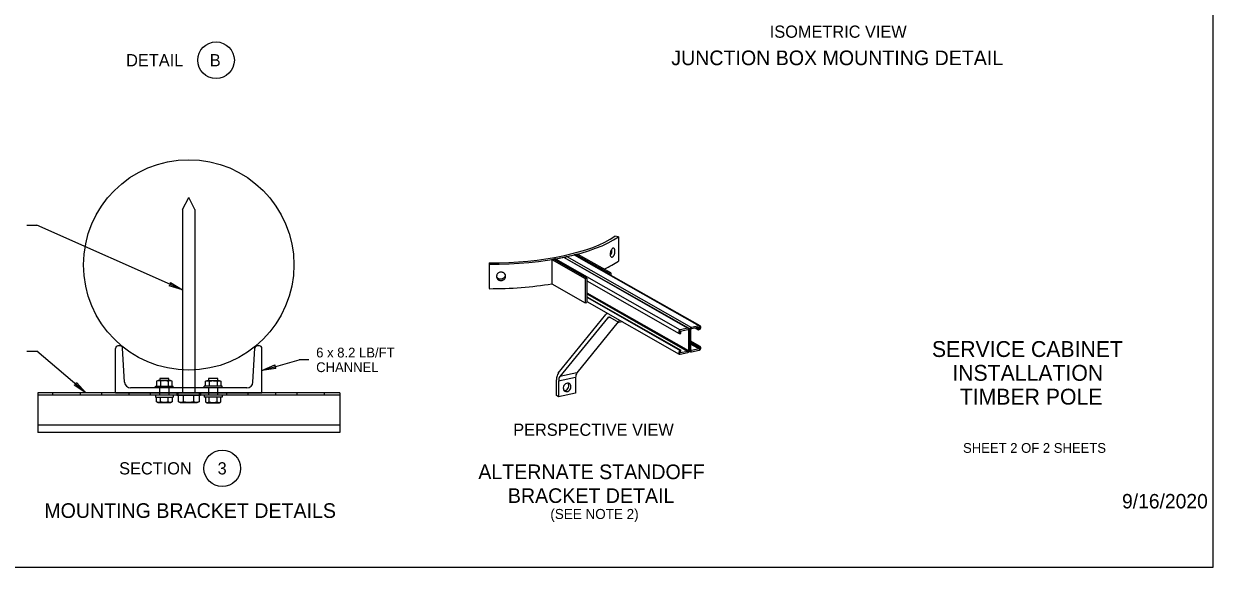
# Model space of a CAD drawing. Extents: x 99862 to 103151, y 100000 to 105076.
# Drawn here: x 101202 to 103151, y 103000 to 103889 of the extents above; entities that cross this region are included whole.
import ezdxf

# ---------------------------------------------------------------- set-up
doc = ezdxf.new("R2010")
doc.units = 0
for name, color, linetype in [('Default', 7, 'Continuous'), ('Level 1', 7, 'Continuous'), ('Level 11', 7, 'Continuous'), ('Level 15', 7, 'Continuous'), ('Level 20', 7, 'Continuous'), ('Level 40', 7, 'Continuous'), ('Level 62', 7, 'Continuous'), ('Level 8', 7, 'Continuous')]:
    doc.layers.add(name, color=color, linetype=linetype)

msp = doc.modelspace()

# ---------------------------------------------------------------- linework, layer by layer
at = {"layer": 'Default'}
for p, q in [((102176.5, 103540.5), (102170.6, 103541.6)), ((102176.5, 103540.5), (102176.5, 103500.6)), ((102163.8, 103481.4), (102109.2, 103512.4)), ((101964.4, 103497.8), (101964.4, 103495.6)), ((101964.4, 103495.6), (101964.4, 103455.7)), ((102067.3, 103503.5), (102121.9, 103472.5)), ((102067.3, 103503.5), (102067.3, 103463.6)), ((102124.7, 103473.1), (102070.2, 103504)), ((102073.2, 103504.5), (102277.8, 103388.3)), ((102086.1, 103507), (102290.3, 103391)), ((102087.7, 103506.7), (102291.9, 103390.7)), ((102091.7, 103508.2), (102295.9, 103392.2)), ((102103.9, 103511), (102308.5, 103394.8)), ((102310.1, 103394.6), (102105.4, 103510.8)), ((102106.5, 103511.7), (102106.5, 103510.2)), ((102106.5, 103511.7), (102161, 103480.8)), ((102161, 103480.8), (102163.8, 103481.4)), ((102161, 103480.8), (102161, 103479.3)), ((102163.8, 103481.4), (102163.8, 103477.7)), ((102067.3, 103463.6), (102121.9, 103432.6)), ((102121.9, 103472.5), (102124.7, 103473.1)), ((102121.9, 103472.5), (102121.9, 103432.6)), ((102124.7, 103473.1), (102124.7, 103433.2)), ((102124.7, 103468.4), (102276.1, 103382.4)), ((102124.7, 103449), (102291.3, 103354.3)), ((102124.7, 103447.1), (102290.3, 103353)), ((102124.7, 103442.4), (102278.9, 103354.8)), ((102124.7, 103441.5), (102277.8, 103354.5)), ((102124.7, 103434.7), (102276.1, 103348.6)), ((102121.9, 103432.6), (102124.7, 103433.2)), ((102077.9, 103317.5), (102155.8, 103413.4)), ((102158.2, 103407.6), (102080.3, 103311.8)), ((102176.1, 103401.1), (102108.3, 103317.7)), ((102162.8, 103408.6), (102158.2, 103407.6)), ((102177.3, 103400.4), (102163.1, 103408.5)), ((102177.3, 103404.8), (102177.3, 103400.4)), ((102182.9, 103401.6), (102177.3, 103400.4)), ((102276.8, 103384.7), (102277.8, 103384.1)), ((102276.9, 103385.5), (102278.9, 103384.4)), ((102290.3, 103391), (102277.8, 103388.3)), ((102277.8, 103386.3), (102290.3, 103389)), ((102278.9, 103384.4), (102277.8, 103384.1)), ((102277.8, 103382.2), (102278.9, 103382.4)), ((102278.9, 103382.4), (102278.9, 103384.4)), ((102291.3, 103388.1), (102291.3, 103354.3)), ((102293.1, 103354.7), (102293.1, 103388.5)), ((102293.1, 103388.5), (102293.1, 103354.7)), ((102294.9, 103355.1), (102294.9, 103388.9)), ((102308.5, 103394.8), (102295.9, 103392.2)), ((102295.9, 103390.2), (102308.5, 103392.9)), ((102302, 103391.5), (102307.4, 103388.4)), ((102304.5, 103392), (102307.4, 103390.4)), ((102305.6, 103392.3), (102308.5, 103390.6)), ((102308.5, 103390.6), (102307.4, 103390.4)), ((102307.4, 103390.4), (102307.4, 103388.4)), ((102307.4, 103388.4), (102308.5, 103388.7)), ((102310.1, 103360.8), (102294.9, 103369.5)), ((102294.9, 103368.8), (102308.5, 103361.1)), ((102294.9, 103367.9), (102307.4, 103360.8)), ((102294.9, 103365.9), (102307.4, 103358.9)), ((102294.9, 103364.6), (102308.5, 103356.9)), ((102308.5, 103356.9), (102295.9, 103354.2)), ((102308.5, 103361.1), (102307.4, 103360.8)), ((102307.4, 103360.8), (102307.4, 103358.9)), ((102307.4, 103358.9), (102308.5, 103359.1)), ((102276.8, 103350.9), (102277.8, 103350.4)), ((102278.9, 103354.8), (102277.8, 103354.5)), ((102290.3, 103353), (102277.8, 103350.4)), ((102277.8, 103352.6), (102278.9, 103352.8)), ((102277.8, 103348.4), (102290.3, 103351.1)), ((102278.9, 103352.8), (102278.9, 103354.8)), ((102292.8, 103353.3), (102294.3, 103352.5)), ((102295, 103354.8), (102295.9, 103354.2)), ((102295.9, 103352.3), (102308.5, 103354.9)), ((102108.3, 103317.7), (102080.3, 103311.8)), ((102074.9, 103280.5), (102074.9, 103306.1)), ((102106.3, 103310.1), (102078.3, 103304.2)), ((102078.3, 103304.2), (102078.3, 103278.6)), ((102106.3, 103310.1), (102106.3, 103284.5)), ((102078.3, 103278.6), (102074.9, 103280.5)), ((102106.3, 103284.5), (102078.3, 103278.6))]:
    msp.add_line(p, q, dxfattribs=at)
for centre, major_axis, ratio, start_param, end_param in [((101966.1, 103577.3), (229.1, 0), 0.346971, 4.705216, 5.816327), ((101966.1, 103577.3), (-235.6, 0), 0.346971, 1.563623, 2.674734), ((101966.1, 103577.3), (235.6, 0), 0.346971, 5.351172, 5.365127), ((101966.1, 103577.3), (235.6, 0), 0.346971, 5.156415, 5.17037), ((101966.1, 103577.3), (235.6, 0), 0.346971, 5.184308, 5.260771), ((102086.1, 103503.9), (1.62, 2.85), 0.800354, 6.283185, 6.900369), ((101966.1, 103577.3), (235.6, 0), 0.346971, 5.260771, 5.337235), ((102091.7, 103505.1), (1.62, 2.85), 0.800354, 0.617184, 1.728937), ((101966.1, 103537.4), (-235.6, 0), 0.346971, 2.485935, 2.674734), ((101966.1, 103537.4), (-235.6, 0), 0.346971, 1.563623, 2.014823), ((102163.1, 103396.2), (-4.1, 19.2), 0.488922, 0.034662, 0.376331), ((102163.1, 103396.2), (2.7, -12.8), 0.488922, 3.141593, 3.517924), ((102163.1, 103396.2), (2.7, -12.8), 0.488922, 2.732526, 3.141593), ((102277.8, 103385.2), (1.62, 2.85), 0.800354, 0.617184, 3.141593), ((102277.8, 103385.2), (1.62, 2.85), 0.800354, 3.141593, 3.758777), ((102277.8, 103385.2), (-0.58, -1.02), 0.800354, 3.758777, 6.283185), ((102277.8, 103385.2), (-0.58, -1.02), 0.800354, 6.283185, 6.900369), ((102290.3, 103387.9), (1.62, 2.85), 0.800354, 6.283185, 6.900369), ((102290.3, 103387.9), (-0.58, -1.02), 0.800354, 3.141593, 3.758777), ((102290.3, 103387.9), (-0.58, -1.02), 0.800354, 2.18798, 3.141593), ((102290.3, 103387.9), (1.62, 2.85), 0.800354, 5.329573, 6.283185), ((102295.9, 103389.1), (1.62, 2.85), 0.800354, 0.617184, 2.18798), ((102295.9, 103389.1), (-0.58, -1.02), 0.800354, 3.758777, 5.329573), ((102308.5, 103391.7), (1.62, 2.85), 0.800354, 6.283185, 6.900369), ((102308.5, 103391.7), (1.62, 2.85), 0.800354, 3.758777, 6.283185), ((102308.5, 103391.7), (-0.58, -1.02), 0.800354, 3.141593, 3.758777), ((102308.5, 103391.7), (-0.58, -1.02), 0.800354, 0.617184, 3.141593), ((102308.5, 103358), (1.62, 2.85), 0.800354, 6.283185, 6.900369), ((102308.5, 103358), (1.62, 2.85), 0.800354, 3.758777, 6.283185), ((102308.5, 103358), (-0.58, -1.02), 0.800354, 3.141593, 3.758777), ((102308.5, 103358), (-0.58, -1.02), 0.800354, 0.617184, 3.141593), ((102277.8, 103351.5), (1.62, 2.85), 0.800354, 0.617184, 3.141593), ((102277.8, 103351.5), (1.62, 2.85), 0.800354, 3.141593, 3.758777), ((102277.8, 103351.5), (-0.58, -1.02), 0.800354, 3.758777, 6.283185), ((102277.8, 103351.5), (-0.58, -1.02), 0.800354, 0, 0.617184), ((102290.3, 103354.1), (1.62, 2.85), 0.800354, 3.758777, 5.329573), ((102290.3, 103354.1), (-0.58, -1.02), 0.800354, 0.617184, 2.18798), ((102295.9, 103355.3), (1.62, 2.85), 0.800354, 2.18798, 3.141593), ((102295.9, 103355.3), (1.62, 2.85), 0.800354, 3.141593, 3.758777), ((102295.9, 103355.3), (-0.58, -1.02), 0.800354, 5.329573, 6.283185), ((102295.9, 103355.3), (-0.58, -1.02), 0.800354, 0, 0.617184), ((102085.2, 103300.3), (-4.1, 19.2), 0.488922, 0.376331, 1.16173), ((102113.1, 103306.2), (2.7, -12.8), 0.488922, 3.517924, 4.303322), ((102085.2, 103300.3), (2.7, -12.8), 0.488922, 3.517924, 4.303322), ((102092.3, 103294), (3.64, 6.4), 0.800354, 0, 3.141593), ((102088.9, 103295.9), (-3.64, -6.4), 0.800354, 0.617184, 2.80219), ((102092.3, 103294), (3.64, 6.4), 0.800354, 5.329573, 6.283185), ((102088.9, 103295.9), (-3.64, -6.4), 0.800354, 0.339402, 0.617184), ((102092.3, 103294), (3.64, 6.4), 0.800354, 3.141593, 5.329573)]:
    msp.add_ellipse(centre, major_axis=major_axis, ratio=ratio, start_param=start_param, end_param=end_param, dxfattribs=at)
for points, degree in [([(102166.9, 103521.5), (102166.5, 103521.3), (102166, 103520.9), (102164.8, 103519.5), (102164.1, 103518), (102163.6, 103516.5), (102163.3, 103515.7), (102163.2, 103514.8), (102163.1, 103514), (102162.7, 103511.3), (102163.3, 103508.7), (102164.6, 103507.8), (102164.6, 103507.8), (102164.7, 103507.7), (102164.8, 103507.7), (102164.9, 103507.6), (102164.9, 103507.6), (102165, 103507.5), (102165.1, 103507.5), (102165.2, 103507.5), (102165.2, 103507.5), (102165.3, 103507.5), (102165.3, 103507.4), (102165.4, 103507.4)], 3), ([(102165, 103519.6), (102165.4, 103516.8), (102164.6, 103513), (102163.1, 103510.7)], 2), ([(102165.4, 103507.4), (102166.1, 103507.3), (102167, 103507.6), (102167.8, 103508.4), (102168.5, 103509.2), (102169.2, 103510.3), (102169.7, 103511.6), (102170.4, 103513.4), (102170.7, 103515.5), (102170.7, 103517.4), (102170.6, 103519.2), (102170.1, 103520.7), (102169.3, 103521.4), (102169.2, 103521.4), (102169.2, 103521.5), (102169.1, 103521.5), (102169, 103521.6), (102169, 103521.6), (102168.9, 103521.7), (102168.8, 103521.7), (102168.8, 103521.7), (102168.7, 103521.8), (102168.6, 103521.8), (102168.5, 103521.8), (102168.4, 103521.8), (102168.4, 103521.8), (102168.4, 103521.8), (102168.4, 103521.8)], 3), ([(102168.4, 103521.8), (102168, 103521.9), (102167.4, 103521.8), (102166.9, 103521.5)], 2), ([(102073.2, 103504.5), (102073.1, 103504.5), (102073, 103504.5), (102072.9, 103504.5), (102072.8, 103504.4), (102072.6, 103504.4), (102072.4, 103504.3), (102072, 103504.1), (102071.6, 103503.8), (102071.3, 103503.4)], 3), ([(102105.4, 103510.8), (102105, 103511.1), (102104.4, 103511.2), (102103.9, 103511)], 2), ([(101991.2, 103477.6), (101991, 103478.4), (101990.7, 103479.1), (101990.2, 103479.8), (101989.8, 103480.4), (101989.2, 103481), (101988.6, 103481.4), (101988, 103481.8), (101987.5, 103482.1), (101986.9, 103482.3), (101985, 103483), (101982.9, 103482.9), (101981.1, 103482.1), (101979.1, 103481.3), (101977.5, 103479.6), (101977, 103477.6), (101976.9, 103477.5), (101976.9, 103477.3), (101976.8, 103477.2), (101976.8, 103477), (101976.8, 103476.8), (101976.8, 103476.7), (101976.7, 103476.5), (101976.7, 103476.4), (101976.7, 103476.2), (101976.7, 103476), (101976.7, 103475.9), (101976.7, 103475.7)], 3), ([(101990.8, 103478.7), (101990.8, 103478.6), (101990.8, 103478.4), (101990.8, 103478.3), (101990.8, 103477.9), (101990.8, 103477.5), (101990.7, 103477.2), (101990.6, 103476.6), (101990.5, 103476.1), (101990.2, 103475.7), (101990.2, 103475.5), (101990.1, 103475.4), (101990.1, 103475.3), (101989.8, 103474.7), (101989.4, 103474.2), (101988.9, 103473.7), (101988.1, 103472.8), (101987, 103472.1), (101985.8, 103471.6), (101984.7, 103471.2), (101983.4, 103471.1), (101982.2, 103471.3), (101980.3, 103471.6), (101978.5, 103472.6), (101977.4, 103474.1), (101977.4, 103474.2), (101977.3, 103474.3), (101977.2, 103474.4), (101977.1, 103474.5), (101977.1, 103474.6), (101977, 103474.7), (101976.9, 103474.8), (101976.9, 103474.9), (101976.8, 103475), (101976.8, 103475.1), (101976.7, 103475.2), (101976.7, 103475.3)], 3), ([(101976.7, 103475.7), (101976.7, 103475.2), (101976.7, 103474.7), (101976.9, 103474.2)], 2), ([(101976.9, 103474.2), (101977, 103473.6), (101977.2, 103473.1), (101977.5, 103472.6), (101977.7, 103472.2), (101978, 103471.8), (101978.3, 103471.4), (101979.2, 103470.3), (101980.5, 103469.5), (101981.9, 103469.2), (101983.8, 103468.7), (101986, 103469), (101987.7, 103470), (101988.1, 103470.2), (101988.5, 103470.5), (101988.9, 103470.8), (101990.1, 103471.9), (101991, 103473.4), (101991.3, 103474.9), (101991.3, 103475.1), (101991.3, 103475.2), (101991.3, 103475.4), (101991.3, 103475.5), (101991.4, 103475.7), (101991.4, 103475.8), (101991.4, 103476), (101991.4, 103476.1), (101991.4, 103476.3), (101991.4, 103476.4), (101991.3, 103476.6), (101991.3, 103476.8), (101991.3, 103476.9), (101991.3, 103477.1), (101991.3, 103477.2), (101991.2, 103477.3), (101991.2, 103477.5), (101991.2, 103477.6)], 3)]:
    msp.add_open_spline(points, degree=degree, dxfattribs=at)
at = {"layer": 'Level 1'}
for p, q in [((101462.3, 103585.1), (101472.3, 103605.1)), ((101482.3, 103585.1), (101472.3, 103605.1)), ((101462.3, 103585.1), (101462.3, 103322.6)), ((101482.3, 103585.1), (101482.3, 103322.6)), ((101352.3, 103285.1), (101352.3, 103357.9)), ((101359.9, 103361.9), (101356.3, 103361.9)), ((101367.1, 103302.6), (101363.9, 103358.2)), ((101577.5, 103302.6), (101580.7, 103358.2)), ((101588.3, 103361.9), (101584.7, 103361.9)), ((101592.3, 103285.1), (101592.3, 103357.9)), ((101462.3, 103322.6), (101462.3, 103293.1)), ((101482.3, 103322.6), (101482.3, 103293.1)), ((101352.3, 103285.1), (101592.3, 103285.1)), ((101567.5, 103293.1), (101377.1, 103293.1)), ((101417.7, 103293.1), (101417.7, 103296.1)), ((101417.7, 103296.1), (101446.9, 103296.1)), ((101417.7, 103281.1), (101417.7, 103278.2)), ((101446.9, 103293.1), (101446.9, 103296.1)), ((101446.9, 103281.1), (101446.9, 103278.2)), ((101452.8, 103285.1), (101452.8, 103281.1)), ((101452.8, 103281.1), (101491.8, 103281.1)), ((101462.3, 103293.1), (101462.3, 103285.1)), ((101482.3, 103293.1), (101482.3, 103285.1)), ((101491.8, 103285.1), (101491.8, 103281.1)), ((101526.9, 103296.1), (101497.7, 103296.1)), ((101497.7, 103293.1), (101497.7, 103296.1)), ((101497.7, 103281.1), (101497.7, 103278.2)), ((101526.9, 103293.1), (101526.9, 103296.1)), ((101526.9, 103281.1), (101526.9, 103278.2)), ((101417.7, 103278.2), (101446.9, 103278.2)), ((101526.9, 103278.2), (101497.7, 103278.2))]:
    msp.add_line(p, q, dxfattribs=at)
msp.add_lwpolyline([(99862, 102999.5), (103151, 102999.5), (103151, 105075.5), (99862, 105075.5)], close=True, dxfattribs=at)
msp.add_circle((101472.3, 103494.6), 172.3, dxfattribs=at)
for centre, radius, start, end in [((101356.3, 103357.9), 4, 90, 180), ((101359.9, 103357.9), 4, 3.3274, 90), ((101584.7, 103357.9), 4, 90, 176.6726), ((101588.3, 103357.9), 4, 0, 90), ((101377.1, 103303.1), 10, 183.3274, 270), ((101567.5, 103303.1), 10, 270, 356.6726)]:
    msp.add_arc(centre, radius, start, end, dxfattribs=at)
at = {"layer": 'Level 11'}
for p, q in [((101224.8, 103285.1), (101224.8, 103220.1)), ((101719.8, 103285.1), (101224.8, 103285.1)), ((101719.8, 103281.1), (101224.8, 103281.1)), ((101249.8, 103281.1), (101249.8, 103285.1)), ((101294.8, 103281.1), (101294.8, 103285.1)), ((101329.8, 103281.1), (101329.8, 103285.1)), ((101374.8, 103281.1), (101374.8, 103285.1)), ((101409.8, 103281.1), (101409.8, 103285.1)), ((101454.8, 103281.1), (101454.8, 103285.1)), ((101489.8, 103281.1), (101489.8, 103285.1)), ((101534.8, 103281.1), (101534.8, 103285.1)), ((101569.8, 103281.1), (101569.8, 103285.1)), ((101614.8, 103281.1), (101614.8, 103285.1)), ((101649.8, 103281.1), (101649.8, 103285.1)), ((101694.8, 103281.1), (101694.8, 103285.1)), ((101719.8, 103285.1), (101719.8, 103220.1)), ((101719.8, 103232.1), (101224.8, 103232.1)), ((101719.8, 103220.1), (101224.8, 103220.1))]:
    msp.add_line(p, q, dxfattribs=at)
at = {"layer": 'Level 15'}
for p, q in [((101207.2, 103559.4), (101223.2, 103559.4)), ((101462.3, 103453.9), (101223.2, 103559.4)), ((101207.2, 103353.2), (101223.2, 103353.2)), ((101303.8, 103285.1), (101223.2, 103353.2)), ((101592.3, 103321.5), (101653.1, 103339)), ((101669.1, 103339), (101653.1, 103339))]:
    msp.add_line(p, q, dxfattribs=at)
for points in [[(101462.3, 103453.9), (101440.2, 103460.3), (101442.4, 103462.6), (101442.6, 103465.8)], [(101592.3, 103321.5), (101613.4, 103330.7), (101613.3, 103327.5), (101615.1, 103325)], [(101303.8, 103285.1), (101284.5, 103297.6), (101287.2, 103299.2), (101288.3, 103302.1)]]:
    msp.add_lwpolyline(points, close=True, dxfattribs=at)
at = {"layer": 'Level 20'}
for centre in [(101517, 103829.8), (101527.2, 103161.4)]:
    msp.add_circle(centre, 30, dxfattribs=at)
at = {"layer": 'Level 8'}
for p, q in [((101422.3, 103305.5), (101419.7, 103304.1)), ((101419.7, 103304.1), (101419.7, 103296.1)), ((101442.4, 103305.5), (101422.3, 103305.5)), ((101439.8, 103308.8), (101424.8, 103308.8)), ((101424.8, 103308.8), (101424.8, 103305.5)), ((101426, 103304.1), (101426, 103296.1)), ((101438.6, 103304.1), (101438.6, 103296.1)), ((101439.8, 103305.5), (101439.8, 103308.8)), ((101444.9, 103304.1), (101442.4, 103305.5)), ((101444.9, 103296.1), (101444.9, 103304.1)), ((101499.7, 103304.1), (101502.3, 103305.5)), ((101499.7, 103296.1), (101499.7, 103304.1)), ((101502.3, 103305.5), (101522.4, 103305.5)), ((101519.8, 103308.8), (101504.8, 103308.8)), ((101504.8, 103308.8), (101504.8, 103305.5)), ((101506, 103304.1), (101506, 103296.1)), ((101518.6, 103304.1), (101518.6, 103296.1)), ((101519.8, 103305.5), (101519.8, 103308.8)), ((101522.4, 103305.5), (101524.9, 103304.1)), ((101524.9, 103304.1), (101524.9, 103296.1)), ((101424.8, 103281.1), (101424.8, 103293.1)), ((101439.8, 103293.1), (101439.8, 103281.1)), ((101455.6, 103270.4), (101455.6, 103281.1)), ((101463.9, 103270.4), (101463.9, 103281.1)), ((101480.7, 103270.4), (101480.7, 103281.1)), ((101489.1, 103281.1), (101489.1, 103270.4)), ((101504.8, 103293.1), (101504.8, 103281.1)), ((101519.8, 103281.1), (101519.8, 103293.1)), ((101419.7, 103270.1), (101419.7, 103278.2)), ((101422.3, 103268.8), (101419.7, 103270.1)), ((101442.4, 103268.8), (101422.3, 103268.8)), ((101426, 103270.1), (101426, 103278.2)), ((101438.6, 103270.1), (101438.6, 103278.2)), ((101444.9, 103270.1), (101442.4, 103268.8)), ((101444.9, 103278.2), (101444.9, 103270.1)), ((101458.9, 103268.6), (101455.6, 103270.4)), ((101485.7, 103268.6), (101458.9, 103268.6)), ((101489.1, 103270.4), (101485.7, 103268.6)), ((101499.7, 103278.2), (101499.7, 103270.1)), ((101499.7, 103270.1), (101502.3, 103268.8)), ((101502.3, 103268.8), (101522.4, 103268.8)), ((101506, 103270.1), (101506, 103278.2)), ((101518.6, 103270.1), (101518.6, 103278.2)), ((101522.4, 103268.8), (101524.9, 103270.1)), ((101524.9, 103270.1), (101524.9, 103278.2))]:
    msp.add_line(p, q, dxfattribs=at)
for points in [[(101426, 103304.1), (101425, 103304.7), (101424, 103305), (101421.8, 103305), (101420.8, 103304.7), (101419.7, 103304.1)], [(101438.6, 103304.1), (101437.6, 103304.4), (101436.6, 103304.6), (101434.5, 103305), (101433.4, 103305), (101430.2, 103305), (101428.1, 103304.7), (101426, 103304.1)], [(101444.9, 103304.1), (101443.9, 103304.7), (101442.8, 103305), (101440.7, 103305), (101439.6, 103304.7), (101438.6, 103304.1)], [(101499.7, 103304.1), (101500.8, 103304.7), (101501.8, 103305), (101504, 103305), (101505, 103304.7), (101506, 103304.1)], [(101506, 103304.1), (101507.1, 103304.4), (101508.1, 103304.6), (101510.2, 103305), (101511.3, 103305), (101514.4, 103305), (101516.6, 103304.7), (101518.6, 103304.1)], [(101518.6, 103304.1), (101519.6, 103304.7), (101520.7, 103305), (101522.8, 103305), (101523.9, 103304.7), (101524.9, 103304.1)], [(101426, 103270.1), (101425, 103269.6), (101424, 103269.2), (101421.8, 103269.2), (101420.8, 103269.6), (101419.7, 103270.1)], [(101438.6, 103270.1), (101437.6, 103269.9), (101436.6, 103269.6), (101434.5, 103269.3), (101433.4, 103269.2), (101430.2, 103269.2), (101428.1, 103269.6), (101426, 103270.1)], [(101444.9, 103270.1), (101443.9, 103269.6), (101442.8, 103269.2), (101440.7, 103269.2), (101439.6, 103269.6), (101438.6, 103270.1)], [(101463.9, 103270.4), (101462.6, 103269.6), (101461.2, 103269.2), (101458.3, 103269.2), (101456.9, 103269.6), (101455.6, 103270.4)], [(101480.7, 103270.4), (101479.3, 103270), (101478, 103269.7), (101475.2, 103269.3), (101473.7, 103269.2), (101469.5, 103269.2), (101466.7, 103269.6), (101463.9, 103270.4)], [(101489.1, 103270.4), (101487.7, 103269.6), (101486.3, 103269.2), (101483.5, 103269.2), (101482.1, 103269.6), (101480.7, 103270.4)], [(101499.7, 103270.1), (101500.8, 103269.6), (101501.8, 103269.2), (101504, 103269.2), (101505, 103269.6), (101506, 103270.1)], [(101506, 103270.1), (101507.1, 103269.9), (101508.1, 103269.6), (101510.2, 103269.3), (101511.3, 103269.2), (101514.4, 103269.2), (101516.6, 103269.6), (101518.6, 103270.1)], [(101518.6, 103270.1), (101519.6, 103269.6), (101520.7, 103269.2), (101522.8, 103269.2), (101523.9, 103269.6), (101524.9, 103270.1)]]:
    msp.add_open_spline(points, degree=3, dxfattribs=at)

# ---------------------------------------------------------------- texts
at = {"layer": 'Level 15'}
msp.add_text('9/16/2020', height=23.62, dxfattribs=at).set_placement((103001.6, 103095.8))
at = {"layer": 'Level 20'}
for s, height, p in [('ISOMETRIC VIEW', 20, (102424.4, 103866.6)), ('JUNCTION BOX MOUNTING DETAIL', 24, (102263, 103821.7)), ('DETAIL', 20, (101369.7, 103819.8)), ('B', 20, (101506.8, 103819.8)), ('PERSPECTIVE VIEW', 20, (102004, 103214.7)), ('SECTION', 20, (101358.3, 103151.4)), ('3', 20, (101519.6, 103151.4)), ('ALTERNATE STANDOFF ', 24, (101946.8, 103143.7)), ('BRACKET DETAIL', 24, (101995.2, 103104.7)), ('MOUNTING BRACKET DETAILS', 24, (101235.6, 103080.2))]:
    msp.add_text(s, height=height, dxfattribs=at).set_placement(p)
for s, p in [('6 x 8.2 LB/FT', (101681.1, 103343)), ('CHANNEL', (101681.1, 103319))]:
    msp.add_text(s, height=16, rotation=360, dxfattribs=at).set_placement(p)
at = {"layer": 'Level 40'}
msp.add_text('(SEE NOTE 2)', height=16.5, dxfattribs=at).set_placement((102064.8, 103078.4))
at = {"layer": 'Level 62'}
for s, height, p in [('SERVICE CABINET', 26, (102690.1, 103343.8)), ('INSTALLATION', 26, (102723.4, 103304.8)), ('TIMBER POLE', 26, (102735.7, 103265.8)), ('SHEET 2 OF 2 SHEETS', 16, (102741.1, 103186.8))]:
    msp.add_text(s, height=height, dxfattribs=at).set_placement(p)

doc.saveas('drawing.dxf')
